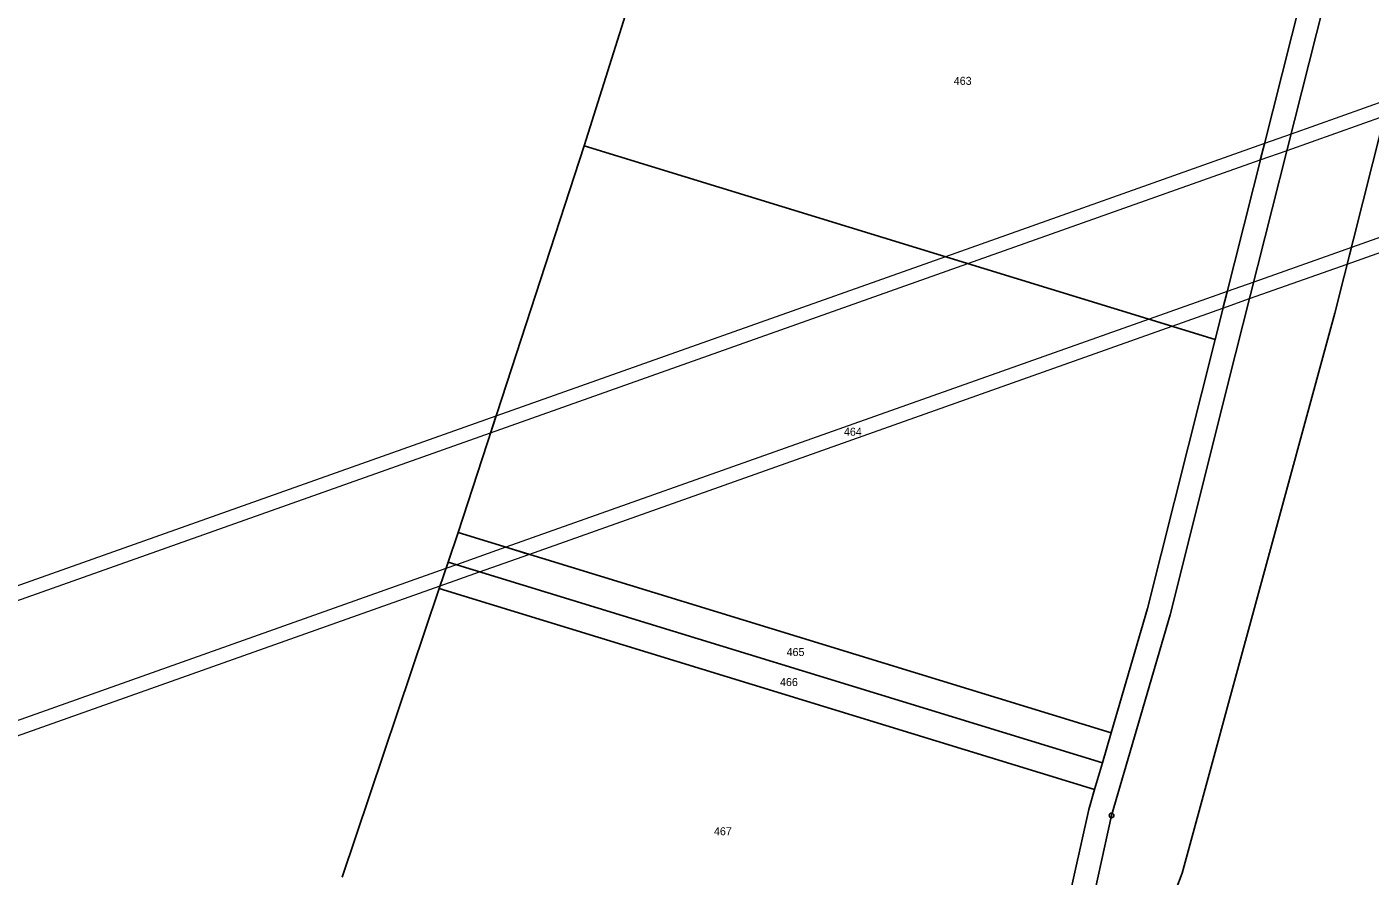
# Model space of a CAD drawing. Extents: x -759947 to -757003, y -1019641 to -1017100.
# Drawn here: x -758551.5 to -758266.2, y -1018616.8 to -1018436.3 of the extents above; entities that cross this region are included whole.
import ezdxf

# ---------------------------------------------------------------- set-up
doc = ezdxf.new("R2010")
doc.units = 0
doc.header["$LTSCALE"] = 0.68
for name, color, linetype, lineweight in [('1', 7, 'Continuous', 25), ('13', 7, 'Continuous', 13), ('8', 7, 'Continuous', 25)]:
    doc.layers.add(name, color=color, linetype=linetype, lineweight=lineweight)
doc.layers.add('2', color=7, linetype='Continuous')

msp = doc.modelspace()

# ---------------------------------------------------------------- linework, layer by layer
at = {"layer": '1'}
for p, q in [((-758410.22, -1018389.3), (-758433.13, -1018461.61)), ((-758299.1, -1018502.73), (-758280.64, -1018429.59)), ((-758275.99, -1018431.61), (-758294.72, -1018505.81)), ((-758273.66, -1018497.18), (-758258.86, -1018438.39)), ((-758433.13, -1018461.61), (-758459.9, -1018543.8)), ((-758433.13, -1018461.61), (-758299.1, -1018502.73)), ((-758306.1, -1018616.16), (-758273.66, -1018497.18)), ((-758313.45, -1018559.93), (-758299.1, -1018502.73)), ((-758294.72, -1018505.81), (-758308.62, -1018561.24)), ((-758462.01, -1018550.08), (-758459.9, -1018543.8)), ((-758459.9, -1018543.8), (-758321.17, -1018586.36)), ((-758462.01, -1018550.08), (-758463.88, -1018555.64)), ((-758323.03, -1018592.72), (-758462.01, -1018550.08)), ((-758484.48, -1018617.01), (-758463.88, -1018555.64)), ((-758463.88, -1018555.64), (-758324.68, -1018598.35)), ((-758321.17, -1018586.36), (-758313.45, -1018559.93)), ((-758308.62, -1018561.24), (-758321.08, -1018603.87)), ((-758323.03, -1018592.72), (-758321.17, -1018586.36)), ((-758324.68, -1018598.35), (-758323.03, -1018592.72)), ((-758325.93, -1018602.63), (-758324.68, -1018598.35)), ((-758334.38, -1018640.83), (-758325.93, -1018602.63)), ((-758321.08, -1018603.87), (-758329.53, -1018642.07)), ((-758315.83, -1018642.03), (-758306.1, -1018616.16))]:
    msp.add_line(p, q, dxfattribs=at)
at = {"layer": '13'}
for points in [[(-758166.1, -1018446.29), (-758219.28, -1018465.15), (-758270.14, -1018483.19), (-758271.03, -1018486.73), (-758218.29, -1018468.01), (-758159.17, -1018447.04)], [(-758262.23, -1018451.77), (-758282.93, -1018459.12), (-758288.6, -1018461.13), (-758289.48, -1018464.6), (-758283.81, -1018462.59), (-758263.1, -1018455.24)], [(-758351.58, -1018486.63), (-758289.48, -1018464.6), (-758288.6, -1018461.13), (-758356.35, -1018485.17)], [(-758356.35, -1018485.17), (-758451.84, -1018519.04), (-758453, -1018522.6), (-758351.58, -1018486.63)], [(-758270.14, -1018483.19), (-758290.87, -1018490.55), (-758296.53, -1018492.56), (-758297.42, -1018496.09), (-758291.76, -1018494.08), (-758271.03, -1018486.73)], [(-758308.23, -1018499.93), (-758297.42, -1018496.09), (-758296.53, -1018492.56), (-758313.1, -1018498.43)], [(-758313.1, -1018498.43), (-758449.76, -1018546.91), (-758444.88, -1018548.41), (-758308.23, -1018499.93)], [(-758451.84, -1018519.04), (-758579.22, -1018564.24), (-758671.21, -1018596.88), (-758667.82, -1018598.82), (-758578.23, -1018567.03), (-758453, -1018522.6)], [(-758455.35, -1018552.12), (-758444.88, -1018548.41), (-758449.76, -1018546.91), (-758460.23, -1018550.63)], [(-758455.35, -1018552.12), (-758460.23, -1018550.63), (-758462.46, -1018551.42), (-758463.69, -1018555.08)], [(-758462.46, -1018551.42), (-758570.19, -1018589.63), (-758640.45, -1018614.57), (-758636.98, -1018616.56), (-758569.14, -1018592.5), (-758463.69, -1018555.08)]]:
    msp.add_lwpolyline(points, close=True, dxfattribs=at)
at = {"layer": '8'}
for radius in [0.5, 0.0303]:
    msp.add_circle((-758321.08, -1018603.8699), radius, dxfattribs=at)

# ---------------------------------------------------------------- texts
at = {"layer": '2'}
for s, p in [('463', (-758354.6, -1018448.655)), ('464', (-758377.93, -1018523.205)), ('465', (-758390.11, -1018570.015)), ('466', (-758391.51, -1018576.395)), ('467', (-758405.54, -1018608.095))]:
    msp.add_text(s, height=1.7, dxfattribs=at).set_placement(p)

doc.saveas('drawing.dxf')
